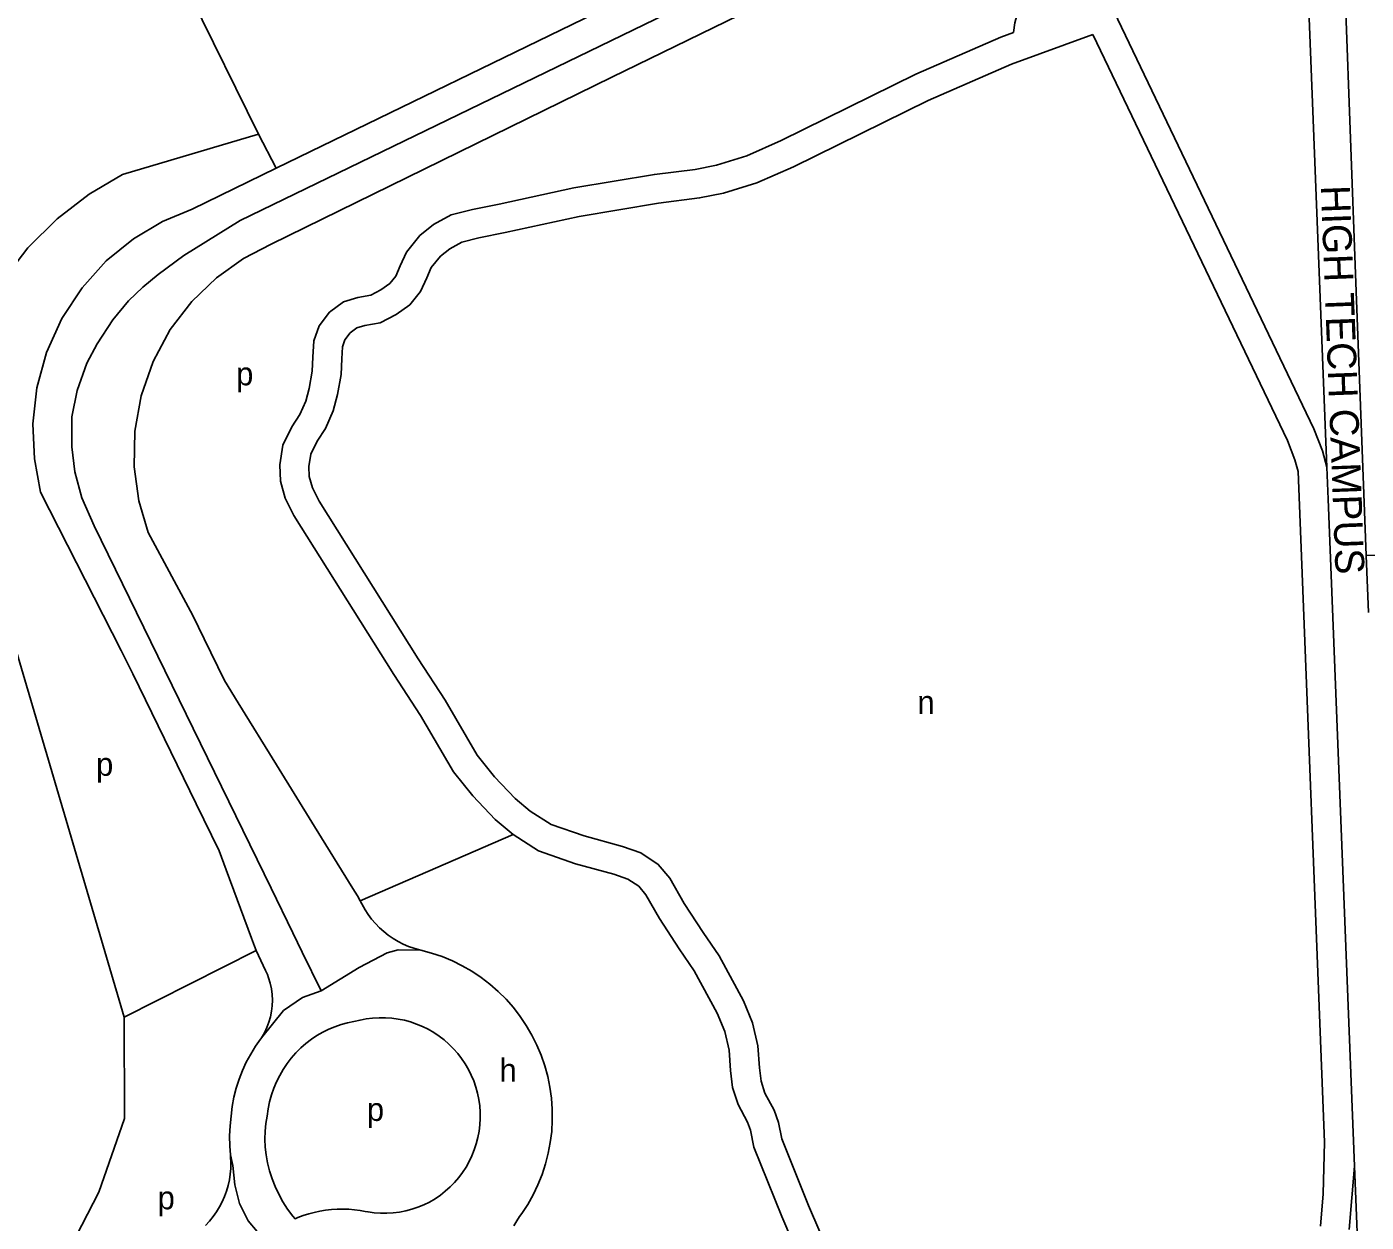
# Model space of a CAD drawing. Extents: x 158358 to 160383, y 379531 to 380764.
# Drawn here: x 159279.5 to 159510.8, y 379710.4 to 379916.8 of the extents above; entities that cross this region are included whole.
import ezdxf

# ---------------------------------------------------------------- set-up
doc = ezdxf.new("R2010")
doc.units = 0
for name, color, linetype in [('BLT_Basislijn', 7, 'Continuous'), ('BLT_Centroide', 7, 'Continuous'), ('BLT_Straatnaam', 7, 'Continuous'), ('BLT_Vlakafsluiter', 7, 'Continuous')]:
    doc.layers.add(name, color=color, linetype=linetype)

msp = doc.modelspace()

# ---------------------------------------------------------------- linework, layer by layer
at = {"layer": 'BLT_Basislijn'}
for p, q in [((159259.52, 380020.21), (159319.52, 379898.27)), ((159422.78, 379928.74), (159380.52, 379908.13)), ((159394.17, 379927.2), (159322.57, 379892.39)), ((159380.52, 379908.13), (159321.72, 379879.27)), ((159319.52, 379898.27), (159296.06, 379891.31)), ((159319.52, 379898.27), (159322.57, 379892.39)), ((159322.57, 379892.39), (159308.06, 379885.34)), ((159515.76, 379825.72), (159510.76, 379825.54)), ((159510.76, 379825.54), (159511.14, 379815.7)), ((159337.06, 379765.91), (159363.46, 379777.33)), ((159296.31, 379745.8), (159319.14, 379757.32))]:
    msp.add_line(p, q, dxfattribs=at)
for points in [[(159325.44, 379760.34), (159321.72, 379768.09), (159291.12, 379830.62), (159289.02, 379835.49), (159287.78, 379839.95), (159287.26, 379844.3), (159287.26, 379849.47), (159288.22, 379854), (159289.89, 379858.72), (159291.65, 379862.09), (159294.39, 379866.21), (159297.06, 379869.48), (159299.52, 379871.84), (159302.19, 379874.04), (159306.6, 379877.33), (159316.34, 379883.36), (159448.26, 379947.41)], [(159506.3, 379944.33), (159508.9, 379874.17), (159510.76, 379825.54)], [(159456.82, 379941.22), (159501.74, 379847.38), (159503.21, 379843.58), (159503.96, 379840.8)], [(159500.05, 379940.35), (159503.96, 379840.8)], [(159449.87, 379915.82), (159450.07, 379917.49), (159450.98, 379920.68), (159452.59, 379924.52), (159454.98, 379927.6), (159456.87, 379929.53)], [(159363.46, 379777.33), (159360.4, 379779.92), (159356.5, 379784.01), (159353.16, 379788.18), (159347.48, 379797.91), (159342.88, 379804.95), (159325.62, 379832.43), (159324.13, 379835.41), (159323.3, 379838.37), (159323.18, 379841.18), (159323.72, 379844.56), (159325.27, 379847.74), (159326.67, 379849.88), (159327.69, 379852.15), (159328.25, 379854.37), (159328.8, 379857.33), (159328.9, 379859.76), (159329.06, 379862.57), (159329.97, 379865.18), (159331.8, 379867.56), (159334.21, 379869.35), (159336.67, 379870.1), (159338.88, 379870.5), (159340.66, 379871.42), (159342.18, 379872.5), (159343.2, 379873.76), (159344, 379875.53), (159345.04, 379877.9), (159347.39, 379880.78), (159349.73, 379882.67), (159352.77, 379884.33), (159356.44, 379885.26), (159361.06, 379886.2), (159373.95, 379889), (159387.87, 379891.33), (159394.88, 379892.2), (159398.59, 379892.94), (159403.8, 379894.55), (159409.75, 379897.18), (159433.02, 379908.62), (159447.68, 379915.02), (159449.87, 379915.82)], [(159418.19, 379704.6), (159414.49, 379713.26), (159409.84, 379724.77), (159409.29, 379727.62), (159408.52, 379729.71), (159406.94, 379732.69), (159406.28, 379734.73), (159406.01, 379737.03), (159405.74, 379740.83), (159404.8, 379744.84), (159403.23, 379748.64), (159399.02, 379756.41), (159396.29, 379760.4), (159393, 379765.44), (159390.51, 379769.78), (159388.53, 379772.18), (159385.54, 379774.16), (159382.36, 379775.27), (159375.75, 379777.08), (159370.07, 379779.07), (159366.43, 379781.37), (159363.83, 379783.56), (159360.27, 379787.3), (159357.29, 379791.02), (159351.73, 379800.54), (159347.09, 379807.65), (159329.98, 379834.89), (159328.82, 379837.22), (159328.27, 379839.17), (159328.2, 379840.89), (159328.54, 379843.04), (159329.63, 379845.27), (159331.06, 379847.47), (159332.43, 379850.5), (159333.13, 379853.31), (159333.78, 379856.76), (159333.89, 379859.51), (159334.01, 379861.58), (159334.43, 379862.78), (159335.34, 379863.96), (159336.49, 379864.82), (159337.85, 379865.23), (159340.52, 379865.72), (159343.27, 379867.14), (159345.64, 379868.83), (159347.49, 379871.12), (159348.56, 379873.49), (159349.34, 379875.26), (159350.94, 379877.22), (159352.52, 379878.49), (159354.62, 379879.64), (159357.56, 379880.39), (159362.09, 379881.31), (159374.89, 379884.08), (159388.59, 379886.38), (159395.67, 379887.26), (159399.82, 379888.08), (159405.55, 379889.86), (159411.86, 379892.65), (159435.13, 379904.08), (159449.54, 379910.38), (159463.58, 379915.52)], [(159463.58, 379915.52), (159497.15, 379845.4), (159498.45, 379842.02), (159498.99, 379840.04)], [(159296.06, 379891.31), (159290.29, 379887.92), (159284.78, 379883.68), (159279.7, 379878.63), (159275.23, 379872.83), (159271.52, 379866.4), (159268.7, 379859.5), (159267.43, 379843.69)], [(159308.06, 379885.34), (159302.95, 379883.19), (159297.95, 379880.21), (159293.24, 379876.38), (159289.05, 379871.75), (159285.56, 379866.43), (159282.93, 379860.59), (159281.26, 379854.45), (159280.57, 379848.24), (159280.82, 379842.19), (159281.9, 379836.46), (159295.83, 379809.14)], [(159321.72, 379879.27), (159316.91, 379876.79), (159312.27, 379873.5), (159307.99, 379869.39), (159304.27, 379864.53), (159301.32, 379859.04), (159299.26, 379853.11), (159298.18, 379846.97), (159298.07, 379840.85), (159298.88, 379834.97), (159300.49, 379829.51), (159308.15, 379815.15)], [(159503.96, 379840.8), (159504.18, 379835.27)], [(159498.99, 379840.04), (159503.57, 379724.19)], [(159504.18, 379835.27), (159508.74, 379720.04)], [(159272.15, 379827.69), (159296.31, 379745.8)], [(159337.06, 379765.91), (159336.61, 379766.72), (159335.81, 379768), (159329.21, 379778.69), (159322.61, 379789.38), (159316, 379800.06), (159313.63, 379803.91), (159310.12, 379811.1), (159308.15, 379815.15)], [(159295.83, 379809.14), (159297.81, 379805.09), (159303.29, 379793.86), (159308.77, 379782.63), (159312.71, 379774.54), (159313.93, 379771.24), (159318.29, 379759.45), (159318.81, 379758.04), (159319.14, 379757.32)], [(159413.56, 379702.72), (159409.87, 379711.35), (159405.03, 379723.35), (159404.46, 379726.27), (159403.94, 379727.67), (159402.32, 379730.73), (159401.37, 379733.65), (159401.03, 379736.56), (159400.78, 379740.08), (159400.02, 379743.3), (159398.71, 379746.49), (159394.75, 379753.8), (159392.13, 379757.62), (159388.73, 379762.83), (159386.38, 379766.93), (159385.15, 379768.43), (159383.3, 379769.65), (159380.88, 379770.49), (159374.27, 379772.3), (159367.88, 379774.53), (159363.46, 379777.33)], [(159347.56, 379757.37), (159346.36, 379757.69), (159345.42, 379758.02), (159344.49, 379758.41), (159343.6, 379758.86), (159342.74, 379759.37), (159341.92, 379759.94), (159341.13, 379760.56), (159340.39, 379761.23), (159339.7, 379761.94), (159339.05, 379762.71), (159338.45, 379763.51), (159337.95, 379764.3), (159337.64, 379764.87), (159337.06, 379765.91)], [(159330.33, 379750.32), (159327.05, 379757), (159325.44, 379760.34)], [(159319.14, 379757.32), (159320.71, 379753.84), (159321.04, 379753.15), (159321.25, 379752.59), (159321.53, 379751.66), (159321.74, 379750.7), (159321.86, 379749.73), (159321.91, 379748.75), (159321.87, 379747.77), (159321.76, 379746.8), (159321.57, 379745.84), (159321.3, 379744.9), (159320.95, 379743.98), (159320.53, 379743.09), (159320.04, 379742.25)], [(159363.61, 379709.77), (159364.1, 379710.62), (159364.59, 379711.36), (159364.95, 379711.86), (159365.99, 379713.46), (159366.93, 379715.13), (159367.75, 379716.85), (159368.47, 379718.63), (159369.06, 379720.44), (159369.54, 379722.3), (159369.89, 379724.17), (159370.13, 379726.07), (159370.24, 379727.98), (159370.22, 379729.89), (159370.08, 379731.8), (159369.82, 379733.69), (159369.44, 379735.57), (159368.93, 379737.41), (159368.31, 379739.22), (159367.57, 379740.98), (159366.71, 379742.69), (159365.75, 379744.34), (159364.69, 379745.93), (159363.52, 379747.45), (159362.25, 379748.88), (159360.9, 379750.23), (159359.46, 379751.49), (159357.94, 379752.65), (159356.35, 379753.71), (159354.7, 379754.67), (159352.98, 379755.52), (159351.22, 379756.25), (159349.41, 379756.87), (159347.56, 379757.37)], [(159271.86, 379679.96), (159273.32, 379682.86), (159279.82, 379693.13), (159285.05, 379702.13), (159291.93, 379715.56), (159296.39, 379728.28), (159296.31, 379745.8)], [(159320.04, 379742.25), (159319.58, 379741.58), (159319.02, 379740.77), (159318.17, 379739.43), (159317.41, 379738.03), (159316.74, 379736.58), (159316.16, 379735.08), (159315.67, 379733.54), (159315.28, 379731.96), (159314.99, 379730.36), (159314.8, 379728.72)], [(159508.74, 379720.04), (159510.15, 379684.35), (159510.58, 379680.95), (159511.63, 379677.83), (159512.96, 379675.4), (159515.12, 379672.76), (159517.23, 379670.91), (159520.09, 379669.22), (159523.31, 379668.22), (159525, 379667.9), (159526.69, 379667.74), (160139.53, 379691.14), (160142.9, 379691.52), (160144.79, 379692.1), (160146.54, 379692.75), (160148.23, 379693.53), (160149.78, 379694.5), (160152.48, 379696.8), (160183.67, 379730.79)], [(159314.8, 379728.72), (159314.6, 379727.01), (159314.51, 379725.28), (159314.54, 379723.53), (159314.66, 379722.04)], [(159503.57, 379724.19), (159503.32, 379715.27), (159502.85, 379709.72)], [(159314.66, 379722.04), (159314.7, 379721.67), (159314.74, 379720.67), (159314.73, 379719.67), (159314.64, 379718.67), (159314.49, 379717.68), (159314.27, 379716.71), (159313.99, 379715.75), (159313.65, 379714.81), (159313.24, 379713.9), (159312.78, 379713.01), (159312.25, 379712.16), (159311.67, 379711.35), (159311.04, 379710.57), (159310.36, 379709.84)], [(159508.74, 379720.04), (159507.82, 379709.13)]]:
    msp.add_lwpolyline(points, dxfattribs=at)
msp.add_lwpolyline([(159337.91, 379712.25), (159338.42, 379712.15), (159339.5, 379712.01), (159340.59, 379711.93), (159341.68, 379711.93), (159342.77, 379712), (159343.85, 379712.14), (159344.93, 379712.35), (159345.99, 379712.63), (159347.03, 379712.97), (159348.05, 379713.39), (159349.04, 379713.87), (159350, 379714.42), (159350.91, 379715.04), (159351.77, 379715.73), (159352.59, 379716.47), (159353.36, 379717.26), (159354.08, 379718.1), (159354.74, 379718.98), (159355.34, 379719.91), (159355.88, 379720.87), (159356.36, 379721.87), (159356.77, 379722.89), (159357.11, 379723.94), (159357.39, 379725.01), (159357.59, 379726.09), (159357.73, 379727.19), (159357.79, 379728.29), (159357.78, 379729.39), (159357.7, 379730.49), (159357.55, 379731.59), (159357.33, 379732.67), (159357.04, 379733.73), (159356.68, 379734.78), (159356.25, 379735.79), (159355.76, 379736.78), (159355.2, 379737.73), (159354.59, 379738.65), (159353.91, 379739.52), (159353.18, 379740.35), (159352.4, 379741.13), (159351.57, 379741.86), (159350.69, 379742.53), (159349.78, 379743.14), (159348.82, 379743.7), (159347.83, 379744.19), (159346.81, 379744.61), (159345.77, 379744.97), (159344.7, 379745.25), (159343.62, 379745.47), (159342.53, 379745.62), (159341.43, 379745.7), (159340.32, 379745.7), (159339.22, 379745.64), (159338.13, 379745.5), (159337.04, 379745.29), (159334.88, 379744.8), (159333.79, 379744.51), (159332.71, 379744.15), (159331.65, 379743.71), (159330.62, 379743.2), (159329.61, 379742.62), (159328.64, 379741.97), (159327.7, 379741.25), (159326.8, 379740.47), (159325.96, 379739.62), (159325.16, 379738.71), (159324.44, 379737.77), (159323.78, 379736.78), (159323.17, 379735.74), (159322.63, 379734.65), (159322.16, 379733.53), (159321.76, 379732.37), (159321.43, 379731.18), (159321.17, 379729.96), (159321, 379728.72), (159321, 379728.71), (159320.78, 379727.41), (159320.66, 379726.08), (159320.63, 379724.73), (159320.68, 379723.36), (159320.83, 379721.99), (159321.08, 379720.61), (159321.42, 379719.24), (159321.85, 379717.88), (159322.38, 379716.53), (159323.01, 379715.21), (159323.73, 379713.92), (159324.55, 379712.66), (159325.46, 379711.45), (159325.84, 379710.99), (159326.29, 379711.17), (159327.23, 379711.52), (159328.18, 379711.83), (159329.15, 379712.08), (159330.12, 379712.29), (159331.11, 379712.45), (159332.11, 379712.56), (159333.1, 379712.63), (159334.1, 379712.64), (159335.1, 379712.61), (159336.1, 379712.52), (159337.09, 379712.39)], close=True, dxfattribs=at)
at = {"layer": 'BLT_Vlakafsluiter'}
for p, q in [((159336.92, 379754.39), (159341.7, 379756.93)), ((159341.7, 379756.93), (159343.63, 379757.42)), ((159343.63, 379757.42), (159347.56, 379757.37)), ((159330.33, 379750.32), (159336.92, 379754.39)), ((159327.13, 379749.18), (159330.33, 379750.32)), ((159323.85, 379746.92), (159327.13, 379749.18)), ((159320.04, 379742.25), (159323.85, 379746.92))]:
    msp.add_line(p, q, dxfattribs=at)
msp.add_lwpolyline([(159314.66, 379722.04), (159315.09, 379720.15), (159315.45, 379716.84), (159316.25, 379713.61), (159317.71, 379710.62), (159319.29, 379708.77)], dxfattribs=at)

# ---------------------------------------------------------------- texts
at = {"layer": 'BLT_Centroide'}
for s, p in [('p', (159315.65, 379854.91)), ('n', (159433.27, 379798.17)), ('p', (159291.47, 379787.48)), ('h', (159361.12, 379734.63)), ('p', (159338.22, 379727.87)), ('p', (159302.09, 379712.61))]:
    msp.add_text(s, height=4, dxfattribs=at).set_placement(p)
at = {"layer": 'BLT_Straatnaam'}
msp.add_text('HIGH TECH CAMPUS', height=5, rotation=272.1866, dxfattribs=at).set_placement((159502.92, 379889.37))

doc.saveas('drawing.dxf')
